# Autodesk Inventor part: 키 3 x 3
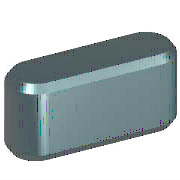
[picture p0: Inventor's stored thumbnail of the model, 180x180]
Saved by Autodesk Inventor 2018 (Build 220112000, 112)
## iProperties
Created: 2012-02
Part Number: 키 3 x 3
Material: 강철, 연강
Description: 키 및 해당 키홈
Document SubType Name: Modeling
Standard: KS B 1311
Designer: mduedu
Standards Organization: KS
Language: ko-KR
Size Designation: 3 x 3 x 12
Categories: <MemberInstance><Categories><Category DisplayName="샤프트 부품" InternalName="7f7aeb1f-a693-4053-b835-cee3144e0d98" Mnemonic="SHFT"><Category DisplayName="키" Interna
Density: 7.86 g/cm^3
Mass: 0.790122 g
Surface Area: 1.42216 cm^2
Volume: 0.100524 cm^3
Appearance: 노란색
IsCustomPart: 1
Author: mduedu
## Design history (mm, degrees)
workplane "Work Plane1"
workplane "Work Plane2"
sketch "스케치1"
  geometry: L1 (1.5, 1.5)-(10.5, 1.5); L2 (10.5, -1.5)-(1.5, -1.5); L3 (0, 9.4)-(0, -7.4) reference; L4 (-5, 0)-(30, 0) reference; L5 (12, 0)-(12, 7); A1 r 1.5 centre (1.5, 0) between (1.5, 1.5) and (1.5, -1.5); A2 r 1.5 centre (10.5, 0) between (10.5, -1.5) and (10.5, 1.5)
  constraints: 6 end point, 5 point on circle, 4 tangent, 3 point on line, 2 centre point, 1 horizontal, 1 parallel, 1 perpendicular
  dimensions: "d0" = 1.5 radius of A1 (= 0.5 x PB); "d13" = 1.5 radius of A2 (= 0.5 x PB); "d14" = 12 distance between parallel lines of L5 L3 (= NLG)
extrude "본체1" new body sketch "스케치1" taper "d3" = 0 deg; stored distance "d4" = 10
workplane "Work Plane3"
body "Solid1"
chamfer "모따기1" distance "d8" = 0.25 (= PHH); stored, may be unused: second distance "d9" = 0.25 (= PHH), angle "d15" = 45 deg
other parameters: "d1" = -1.8 (= -PNT), "d2" = 1.2 (= PH - PNT), "NLG" = 12 [user parameter; used in 3 equation terms], "PB" = 3 [user parameter; used in 2 equation terms], "PNT" = 1.8 [user parameter; used in 2 equation terms], "PH" = 3 [user parameter; used in 1 equation term], "PHH" = 0.25 [user parameter; used in 2 equation terms], "d10" = 0, "d16" = 0, "d17" = 0, "d18" = 0, "WDMIN" = 8 [user parameter], "PLB2" = 12 (= NLG) [user parameter], "PLB1" = 12 (= NLG) [user parameter], "RR" = 0.08 [user parameter], "PUEB" = 1.4 [user parameter]
